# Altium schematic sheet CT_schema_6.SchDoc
size 277 x 170 mm
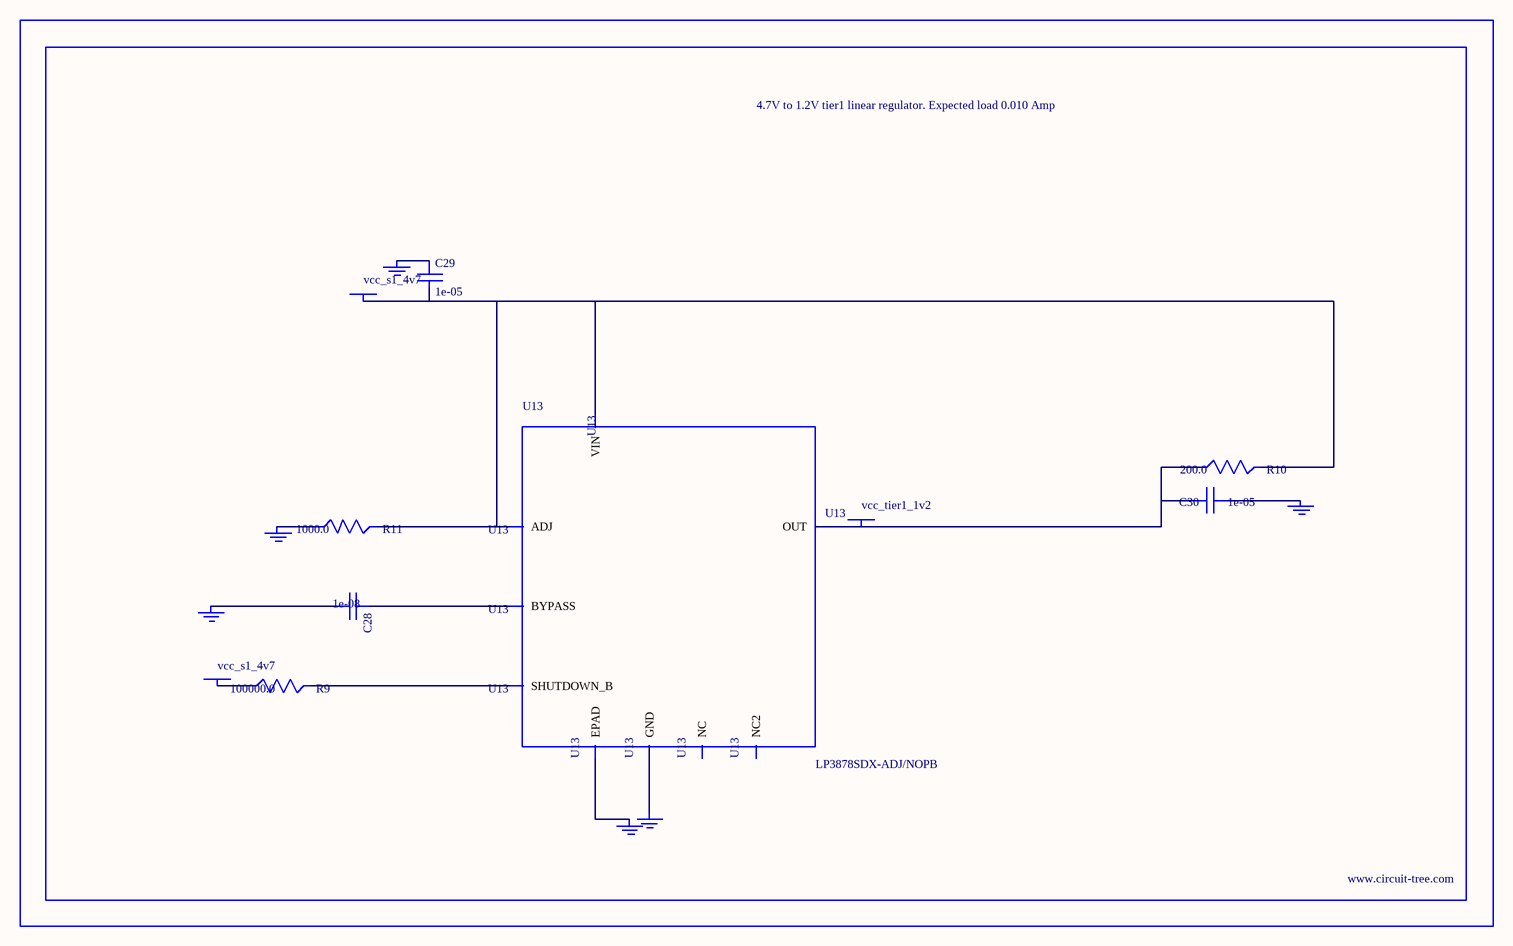
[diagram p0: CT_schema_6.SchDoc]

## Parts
BORDER5  (no value)
C28  1e-08  [C0402]
C29  1e-05  [C1206]
C30  1e-05  [C0805]
GND_INSTANCE_5_0  (no value)
GND_INSTANCE_5_1  (no value)
GND_INSTANCE_5_2  (no value)
GND_INSTANCE_5_3  (no value)
GND_INSTANCE_5_4  (no value)
GND_INSTANCE_5_5  (no value)
POWER_INSTANCE_5_0  vcc_s1_4v7
POWER_INSTANCE_5_1  vcc_s1_4v7
POWER_INSTANCE_5_2  vcc_tier1_1v2
R9  100000.0  [R0603]
R10  200.0  [R0603]
R11  1000.0  [R0603]
U13  LP3878SDX-ADJ/NOPB  [WSON-8]

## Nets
NetC28_1: C28.1 U13.1(BYPASS)
NetC28_2: C28.2 GND_INSTANCE_5_0.0(GND)
NetC29_1: C29.1 GND_INSTANCE_5_1.0(GND)
NetC29_2: C29.2 POWER_INSTANCE_5_0.0(PWR) R10.2 R11.2 U13.4(VIN) U13.6(ADJ)
NetC30_1: C30.1 GND_INSTANCE_5_2.0(GND)
NetC30_2: C30.2 POWER_INSTANCE_5_2.0(PWR) R10.1 U13.5(OUT)
NetGND_INSTANCE_5_3_0: GND_INSTANCE_5_3.0(GND) R11.1
NetGND_INSTANCE_5_4_0: GND_INSTANCE_5_4.0(GND) U13.PAD(EPAD)
NetGND_INSTANCE_5_5_0: GND_INSTANCE_5_5.0(GND) U13.3(GND)
NetPOWER_INSTANCE_5_1_0: POWER_INSTANCE_5_1.0(PWR) R9.1
NetR9_2: R9.2 U13.8(SHUTDOWN_B)

Not connected (* = marked no-connect by the designer): U13 2(NC) 7(NC2)

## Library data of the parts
BORDER5 = BORDER_PAGE5
C28 = C0402C103K3RAC
C29 = C1206C106K3RACTU
C30 = GRM219R60J106ME19D
GND_INSTANCE_5_0-GND_INSTANCE_5_5 = GND
POWER_INSTANCE_5_0-POWER_INSTANCE_5_2 = PWR
R9 = RC0603JR-07100KL
R10 = RC0603JR-07200RL
R11 = RC0603JR-071KL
